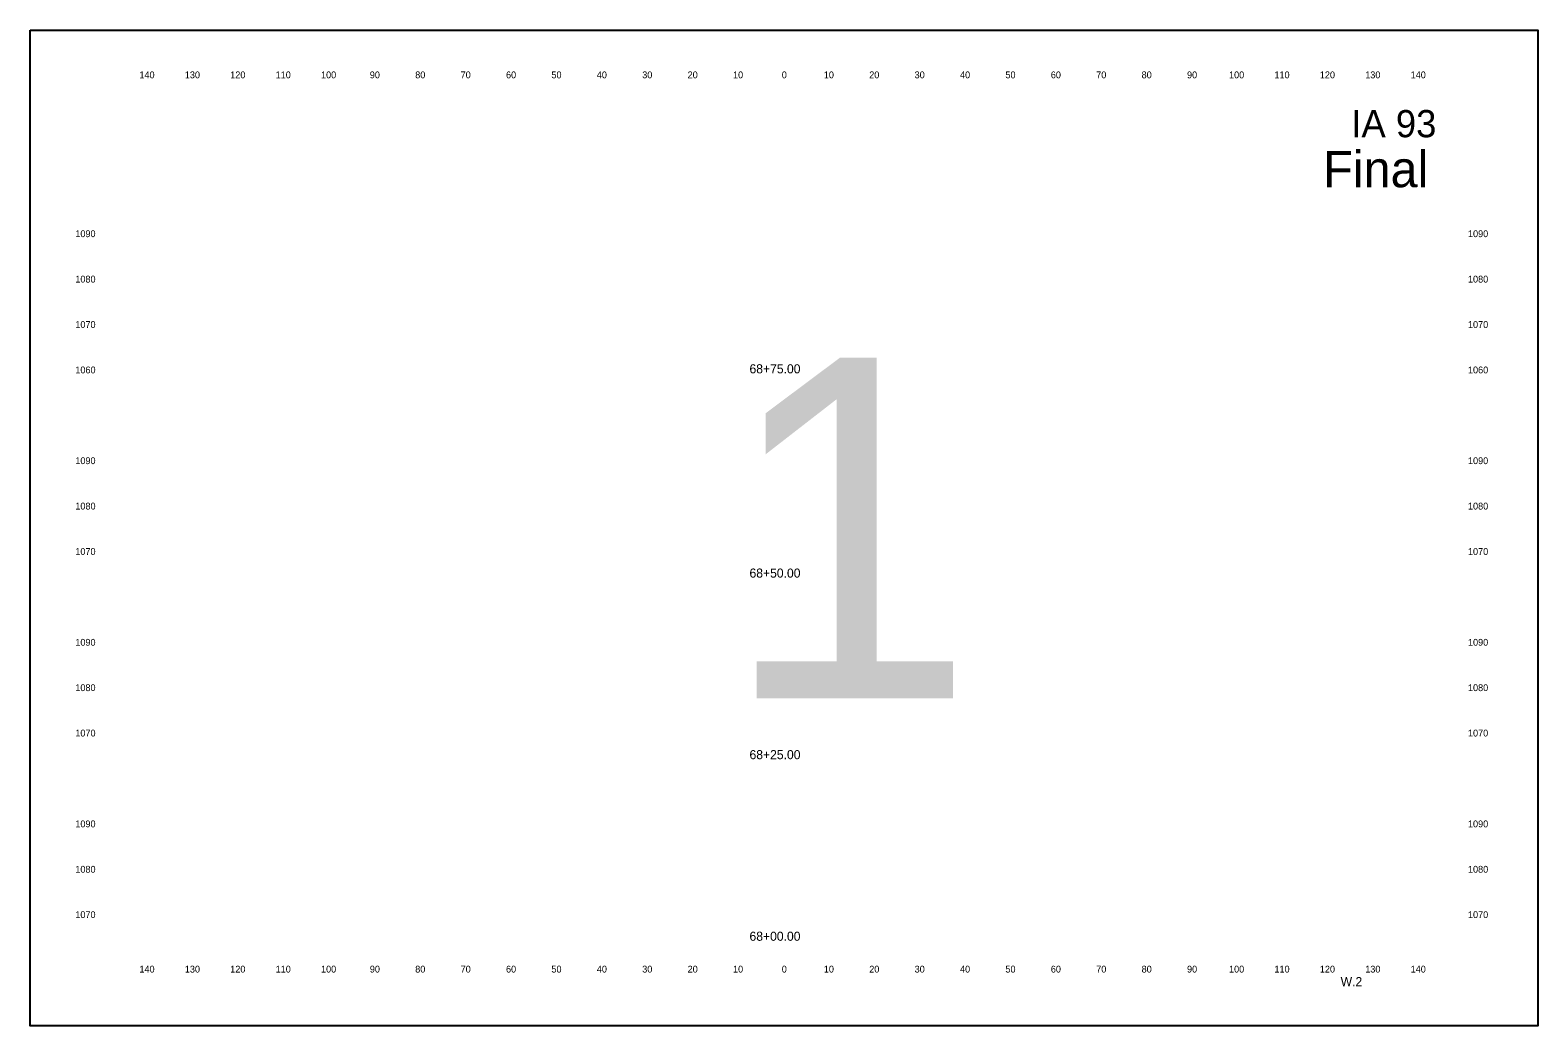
# Model space of a CAD drawing. Extents: x 10123 to 11535, y 9730 to 9950.
# Drawn here: x 10123.2 to 10455.3, y 9730.3 to 9949.6 of the extents above; entities that cross this region are included whole.
import ezdxf

# ---------------------------------------------------------------- set-up
doc = ezdxf.new("R2010")
doc.units = 0
for name, color, linetype in [('dsn3DSubgradeHingePoint', 7, 'Continuous'), ('dsnXSEarthwork', 7, 'Continuous'), ('dsnXsPCCPavement', 7, 'Continuous'), ('dsnXsShldrEarthFill', 7, 'Continuous')]:
    doc.layers.add(name, color=color, linetype=linetype)

msp = doc.modelspace()

# ---------------------------------------------------------------- linework, layer by layer
at = {"layer": 'dsnXsShldrEarthFill'}
msp.add_lwpolyline([(10123.21, 9949.6), (10455.29, 9949.6), (10455.29, 9730.26), (10123.21, 9730.26)], close=True, dxfattribs=at)

# ---------------------------------------------------------------- texts
at = {"layer": 'dsn3DSubgradeHingePoint'}
for s, height, p in [('140', 1.5, (10147.27, 9939)), ('130', 1.5, (10157.27, 9939)), ('120', 1.5, (10167.27, 9939)), ('110', 1.5, (10177.27, 9939)), ('100', 1.5, (10187.27, 9939)), ('90', 1.5, (10198.02, 9939)), ('80', 1.5, (10208.02, 9939)), ('70', 1.5, (10218.02, 9939)), ('60', 1.5, (10228.02, 9939)), ('50', 1.5, (10238.02, 9939)), ('40', 1.5, (10248.02, 9939)), ('30', 1.5, (10258.02, 9939)), ('20', 1.5, (10268.02, 9939)), ('10', 1.5, (10278.02, 9939)), ('0', 1.5, (10288.76, 9939)), ('0', 1.5, (10288.76, 9939)), ('10', 1.5, (10298.02, 9939)), ('20', 1.5, (10308.02, 9939)), ('30', 1.5, (10318.02, 9939)), ('40', 1.5, (10328.02, 9939)), ('50', 1.5, (10338.02, 9939)), ('60', 1.5, (10348.02, 9939)), ('70', 1.5, (10358.02, 9939)), ('80', 1.5, (10368.02, 9939)), ('90', 1.5, (10378.02, 9939)), ('100', 1.5, (10387.27, 9939)), ('110', 1.5, (10397.27, 9939)), ('120', 1.5, (10407.27, 9939)), ('130', 1.5, (10417.27, 9939)), ('140', 1.5, (10427.27, 9939)), ('IA 93', 6, (10414.21, 9926)), ('1090', 1.5, (10133.15, 9904)), ('1090', 1.5, (10439.9, 9904)), ('1080', 1.5, (10133.15, 9894)), ('1080', 1.5, (10439.9, 9894)), ('1070', 1.5, (10133.15, 9884)), ('1070', 1.5, (10439.9, 9884)), ('1060', 1.5, (10133.15, 9874)), ('68+75.00', 2, (10281.65, 9874)), ('1060', 1.5, (10439.9, 9874)), ('1090', 1.5, (10133.15, 9854)), ('1090', 1.5, (10439.9, 9854)), ('1080', 1.5, (10133.15, 9844)), ('1080', 1.5, (10439.9, 9844)), ('1070', 1.5, (10133.15, 9834)), ('1070', 1.5, (10439.9, 9834)), ('68+50.00', 2, (10281.65, 9829)), ('1090', 1.5, (10133.15, 9814)), ('1090', 1.5, (10439.9, 9814)), ('1080', 1.5, (10133.15, 9804)), ('1080', 1.5, (10439.9, 9804)), ('1070', 1.5, (10133.15, 9794)), ('1070', 1.5, (10439.9, 9794)), ('68+25.00', 2, (10281.65, 9789)), ('1090', 1.5, (10133.15, 9774)), ('1090', 1.5, (10439.9, 9774)), ('1080', 1.5, (10133.15, 9764)), ('1080', 1.5, (10439.9, 9764)), ('1070', 1.5, (10133.15, 9754)), ('1070', 1.5, (10439.9, 9754)), ('68+00.00', 2, (10281.65, 9749)), ('140', 1.5, (10147.27, 9742)), ('130', 1.5, (10157.27, 9742)), ('120', 1.5, (10167.27, 9742)), ('110', 1.5, (10177.27, 9742)), ('100', 1.5, (10187.27, 9742)), ('90', 1.5, (10198.02, 9742)), ('80', 1.5, (10208.02, 9742)), ('70', 1.5, (10218.02, 9742)), ('60', 1.5, (10228.02, 9742)), ('50', 1.5, (10238.02, 9742)), ('40', 1.5, (10248.02, 9742)), ('30', 1.5, (10258.02, 9742)), ('20', 1.5, (10268.02, 9742)), ('10', 1.5, (10278.02, 9742)), ('0', 1.5, (10288.76, 9742)), ('0', 1.5, (10288.76, 9742)), ('10', 1.5, (10298.02, 9742)), ('20', 1.5, (10308.02, 9742)), ('30', 1.5, (10318.02, 9742)), ('40', 1.5, (10328.02, 9742)), ('50', 1.5, (10338.02, 9742)), ('60', 1.5, (10348.02, 9742)), ('70', 1.5, (10358.02, 9742)), ('80', 1.5, (10368.02, 9742)), ('90', 1.5, (10378.02, 9742)), ('100', 1.5, (10387.27, 9742)), ('110', 1.5, (10397.27, 9742)), ('120', 1.5, (10407.27, 9742)), ('130', 1.5, (10417.27, 9742)), ('140', 1.5, (10427.27, 9742))]:
    msp.add_text(s, height=height, dxfattribs=at).set_placement(p)
at = {"layer": 'dsnXSEarthwork'}
msp.add_text('Final', height=8, dxfattribs=at).set_placement((10408, 9915))
at = {"layer": 'dsnXsPCCPavement'}
msp.add_text('W.2', height=2, dxfattribs=at).set_placement((10411.86, 9739))
at = {"layer": 'dsnXsShldrEarthFill'}
msp.add_text('1', height=75, dxfattribs=at).set_placement((10275.6, 9802.43))

doc.saveas('drawing.dxf')
